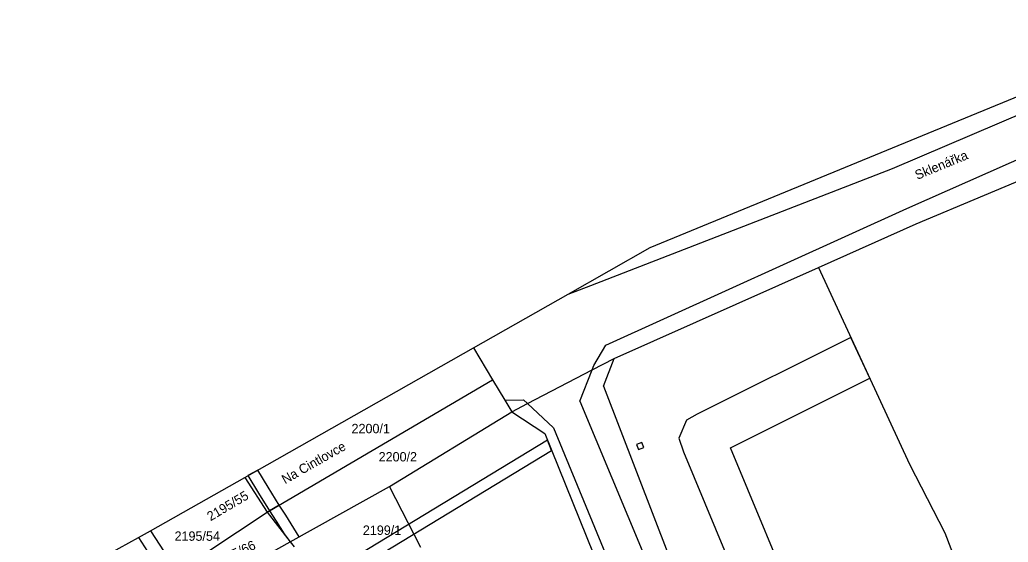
# Model space of a CAD drawing. Extents: x -785744 to -782822, y -1067550 to -1063910.
# Drawn here: x -785002 to -784823, y -1064724.9 to -1064630.2 of the extents above; entities that cross this region are included whole.
import ezdxf

# ---------------------------------------------------------------- set-up
doc = ezdxf.new("R2010")
doc.units = 0
for name, color, linetype in [('Hranice obce', 7, 'Continuous'), ('Hranice parcel', 7, 'Continuous'), ('Parcelní čísla', 7, 'Continuous'), ('Pop_ČP_popisy', 7, 'Continuous'), ('Vnitřní kresba', 7, 'Continuous'), ('Věcná břemena k části', 7, 'Continuous')]:
    doc.layers.add(name, color=color, linetype=linetype)

msp = doc.modelspace()

# ---------------------------------------------------------------- linework, layer by layer
at = {"layer": 'Hranice obce'}
msp.add_lwpolyline([(-785032.64, -1064752.48), (-784999.37, -1064734.37), (-784998.02, -1064733.64), (-784980.54, -1064724.02), (-784978.36, -1064722.79), (-784968.2, -1064717.04), (-784961.28, -1064713.12), (-784919.83, -1064689.66), (-784902.69, -1064679.91), (-784887.87, -1064671.47), (-784857.92, -1064659.16), (-784833.1, -1064648.95), (-784816.19, -1064642)], dxfattribs=at)
at = {"layer": 'Hranice parcel'}
msp.add_line((-784929.41, -1064725.79), (-784935.05, -1064714.76), dxfattribs=at)
for points in [[(-784839.68, -1064667.2), (-784814.9, -1064656.83)], [(-784857.34, -1064675.07), (-784839.68, -1064667.2)], [(-784894.39, -1064691.57), (-784857.34, -1064675.07)], [(-784857.34, -1064675.07), (-784840.88, -1064710.7)], [(-784919.83, -1064689.66), (-784916.38, -1064695.46)], [(-784898.35, -1064693.64), (-784894.39, -1064691.57)], [(-784896.3, -1064696.59), (-784894.39, -1064691.57)], [(-784910.07, -1064699.76), (-784898.35, -1064693.64)], [(-784957.22, -1064719.42), (-784916.38, -1064695.46)], [(-784916.38, -1064695.46), (-784914.2, -1064699.13)], [(-784896.3, -1064696.59), (-784863.25, -1064782.31)], [(-784914.2, -1064699.13), (-784912.93, -1064701.26)], [(-784912.93, -1064701.26), (-784910.07, -1064699.76)], [(-784935.05, -1064714.76), (-784912.93, -1064701.26)], [(-784912.93, -1064701.26), (-784906.94, -1064705.18)], [(-784906.94, -1064705.18), (-784874.09, -1064786.47)], [(-784840.88, -1064710.7), (-784834.5, -1064723.13)], [(-784961.28, -1064713.12), (-784957.22, -1064719.42)], [(-784953.05, -1064724.81), (-784935.05, -1064714.76)], [(-784973.55, -1064730.24), (-784957.22, -1064719.42)], [(-784957.22, -1064719.42), (-784953.05, -1064724.81)], [(-784978.36, -1064722.79), (-784973.55, -1064730.24)], [(-784834.5, -1064723.13), (-784816.3, -1064770.61)], [(-784980.54, -1064724.02), (-784975.63, -1064731.62)], [(-784958.66, -1064727.94), (-784953.05, -1064724.81)], [(-784953.05, -1064724.81), (-784952.36, -1064725.69)]]:
    msp.add_lwpolyline(points, dxfattribs=at)
at = {"layer": 'Vnitřní kresba'}
for points in [[(-784843.94, -1064657.19), (-784780.86, -1064630.23)], [(-784841.33, -1064664.4), (-784777.66, -1064636.24)], [(-784898.6, -1064678.33), (-784843.94, -1064657.19)], [(-784895.86, -1064689.14), (-784841.33, -1064664.4)], [(-784902.69, -1064679.91), (-784898.6, -1064678.33)], [(-784898.03, -1064692.84), (-784895.86, -1064689.14)], [(-784898.35, -1064693.64), (-784898.03, -1064692.84)], [(-784900.6, -1064699.32), (-784898.35, -1064693.64)], [(-784914.2, -1064699.13), (-784910.81, -1064699.08)], [(-784910.81, -1064699.08), (-784910.07, -1064699.76)], [(-784910.07, -1064699.76), (-784905.36, -1064704.12)], [(-784900.6, -1064699.32), (-784865.52, -1064783.36)], [(-784905.36, -1064704.12), (-784871.78, -1064785.44)]]:
    msp.add_lwpolyline(points, dxfattribs=at)
at = {"layer": 'Věcná břemena k části'}
for points in [[(-784851.48, -1064687.75), (-784879.31, -1064701.64)], [(-784850.22, -1064690.47), (-784851.48, -1064687.75)], [(-784849.32, -1064692.43), (-784850.22, -1064690.47)], [(-784848.06, -1064695.15), (-784849.32, -1064692.43)], [(-784873.3, -1064707.75), (-784848.06, -1064695.15)], [(-784879.31, -1064701.64), (-784881.25, -1064702.75)], [(-784881.25, -1064702.75), (-784882.64, -1064706)], [(-784906.45, -1064706.38), (-784943.96, -1064729.14)], [(-784905.7, -1064708.24), (-784906.45, -1064706.38)], [(-784889.38, -1064706.77), (-784890.32, -1064707.13)], [(-784890.32, -1064707.13), (-784889.95, -1064708.06)], [(-784889.01, -1064707.7), (-784889.38, -1064706.77)], [(-784882.64, -1064706), (-784881.82, -1064708.49)], [(-784942.92, -1064730.84), (-784905.7, -1064708.24)], [(-784889.95, -1064708.06), (-784889.01, -1064707.7)], [(-784881.82, -1064708.49), (-784867.98, -1064741.77)], [(-784860.44, -1064738.67), (-784873.3, -1064707.75)], [(-784958.93, -1064711.79), (-784960.71, -1064712.8)], [(-784960.71, -1064712.8), (-784958.77, -1064715.97)], [(-784957.03, -1064714.91), (-784958.93, -1064711.79)], [(-784958.77, -1064715.97), (-784956.77, -1064719.16)], [(-784955.02, -1064718.13), (-784957.03, -1064714.91)], [(-784955.02, -1064718.13), (-784956.77, -1064719.16)], [(-784956.77, -1064719.16), (-784955.02, -1064718.13)], [(-784953.86, -1064719.98), (-784955.02, -1064718.13)], [(-784956.77, -1064719.16), (-784955.58, -1064721.06)], [(-784951.44, -1064723.91), (-784953.86, -1064719.98)], [(-784955.58, -1064721.06), (-784954.17, -1064723.36)], [(-784954.17, -1064723.36), (-784953.05, -1064724.81)], [(-784953.05, -1064724.81), (-784951.44, -1064723.91)]]:
    msp.add_lwpolyline(points, dxfattribs=at)

# ---------------------------------------------------------------- texts
at = {"layer": 'Parcelní čísla'}
for s, p in [('2200/1', (-784941.94, -1064705.12)), ('2200/2', (-784937.03, -1064710.23)), ('2199/1', (-784939.89, -1064723.53))]:
    msp.add_text(s, height=1.7, dxfattribs=at).set_placement(p)
for s, rotation, p in [('2195/55', 30.5574, (-784967.48, -1064721.08)), ('2195/66', 25.0808, (-784966.57, -1064729.46))]:
    msp.add_text(s, height=1.7, rotation=rotation, dxfattribs=at).set_placement(p)
at = {"layer": 'Pop_ČP_popisy'}
for s, rotation, p in [('Sklenářka', 22.4415, (-784839.46, -1064659.24)), ('Na Cintlovce', 29.7051, (-784953.98, -1064714.38))]:
    msp.add_text(s, height=1.7, rotation=rotation, dxfattribs=at).set_placement(p)
msp.add_text('2195/54', height=1.7, dxfattribs=at).set_placement((-784974, -1064724.6))

doc.saveas('drawing.dxf')
